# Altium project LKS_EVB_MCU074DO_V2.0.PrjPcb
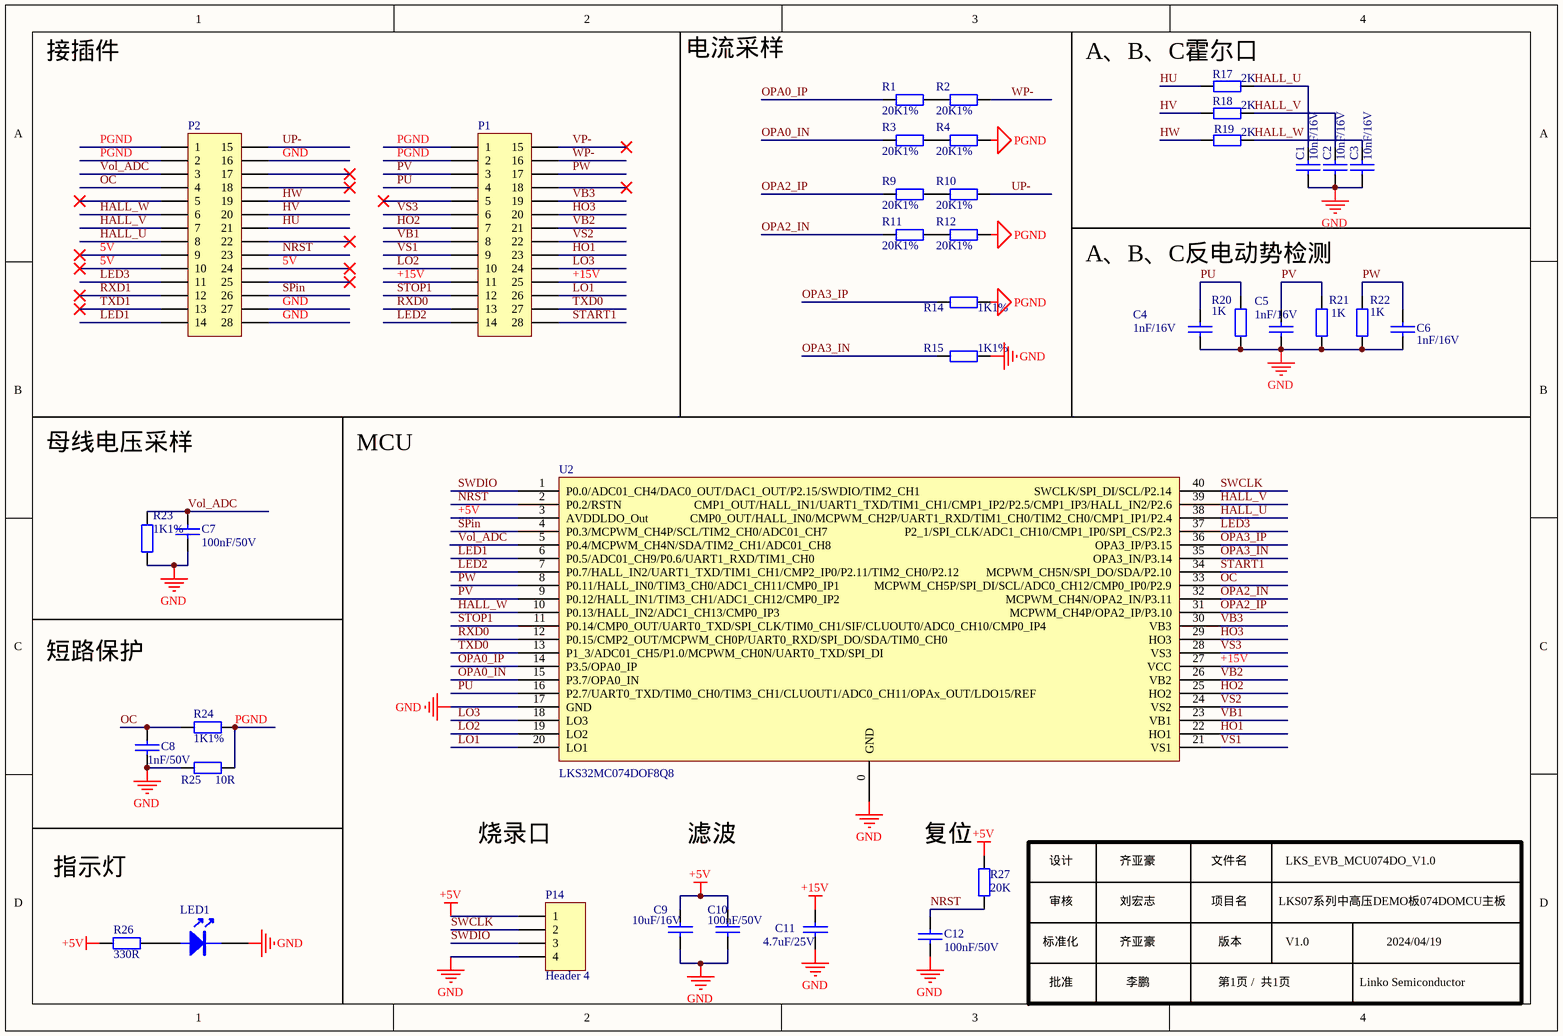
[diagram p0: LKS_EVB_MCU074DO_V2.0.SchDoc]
1 sheet, 38 parts. Net scope: global (net labels, ports and power ports of the same name join across sheets).
Board file: LKS_EVB_MCU074DO_V2.0.PcbDoc

## Sheet LKS_EVB_MCU074DO_V2.0.SchDoc
size A4; SheetNumber: 1; SheetTotal: 1

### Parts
C1  10nF/16V  [0603C]
C2  10nF/16V  [0603C]
C3  10nF/16V  [0603C]
C4  1nF/16V  [0603C]
C5  1nF/16V  [0603C]
C6  1nF/16V  [0603C]
C7  100nF/50V  [0603C]
C8  1nF/50V  [0603C]
C9  10uF/16V  [0603C]
C10  100nF/50V  [0603C]
C11  4.7uF/25V  [0603C]
C12  100nF/50V  [0603C]
LED1  LED  [LED 0603R]  (value not drawn)
P1  Header 14X2A  [HDR 2X14 底层]  (value not drawn)
P2  Header 14X2A  [HDR 2X14 底层]  (value not drawn)
P14  Header 4  [HDR1X4]
R1  20K1%  [0603R]
R2  20K1%  [0603R]
R3  20K1%  [0603R]
R4  20K1%  [0603R]
R9  20K1%  [0603R]
R10  20K1%  [0603R]
R11  20K1%  [0603R]
R12  20K1%  [0603R]
R14  1K1%  [0603R]
R15  1K1%  [0603R]
R17  2K  [0603R]
R18  2K  [0603R]
R19  2K  [0603R]
R20  1K  [0603R]
R21  1K  [0603R]
R22  1K  [0603R]
R23  1K1%  [0603R]
R24  1K1%  [0603R]
R25  10R  [0603R]
R26  330R  [0603R]
R27  20K  [0603R]
U2  LKS32MC074DOF8Q8  [QFN40]

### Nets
+5V: C9.2 C10.2 P14.1 R26.2 R27.2 U2.3(AVDDLDO_Out)
+15V: C11.2 P1.11 P1.25 U2.27(VCC)
GND: C1.2 C2.2 C3.2 C4.2 C5.2 C6.2 C7.1 C8.1 C9.1 C10.1 C11.1 C12.2 LED1.2(K) P2.16 P2.27 P2.28 P14.4 R15.1 R20.2 R21.2 R22.2 R23.1 R25.2 U2.0(GND) U2.17(GND)
PGND: P1.1 P1.2 P2.1 P2.2 R4.1 R12.1 R14.1 R24.2 R25.1
5V: P2.9 P2.10 P2.24
HALL_U: C1.1 P2.8 R17.2 U2.38(CMP0_OUT/HALL_IN0/MCPWM_CH2P/UART1_RXD/TIM1_CH0/TIM2_CH0/CMP1_IP1/P2.4)
HALL_V: C2.1 P2.7 R18.2 U2.39(CMP1_OUT/HALL_IN1/UART1_TXD/TIM1_CH1/CMP1_IP2/P2.5/CMP1_IP3/HALL_IN2/P2.6)
HALL_W: C3.1 P2.6 R19.2 U2.10(P0.13/HALL_IN2/ADC1_CH13/CMP0_IP3)
HO1: P1.23 U2.22(HO1)
HO2: P1.7 U2.25(HO2)
HO3: P1.20 U2.29(HO3)
HU: P2.21 R17.1
HV: P2.20 R18.1
HW: P2.19 R19.1
LED1: P2.14 U2.6(P0.5/ADC01_CH9/P0.6/UART1_RXD/TIM1_CH0)
LED2: P1.14 U2.7(P0.7/HALL_IN2/UART1_TXD/TIM1_CH1/CMP2_IP0/P2.11/TIM2_CH0/P2.12)
LED3: P2.11 U2.37(P2_1/SPI_CLK/ADC1_CH10/CMP1_IP0/SPI_CS/P2.3)
LO1: P1.26 U2.20(LO1)
LO2: P1.10 U2.19(LO2)
LO3: P1.24 U2.18(LO3)
NRST: C12.1 P2.23 R27.1 U2.2(P0.2/RSTN)
OC: C8.2 P2.4 R24.1 U2.33(MCPWM_CH5P/SPI_DI/SCL/ADC0_CH12/CMP0_IP0/P2.9)
OPA0_IN: R3.2 U2.15(P3.7/OPA0_IN)
OPA0_IP: R1.2 U2.14(P3.5/OPA0_IP)
OPA2_IN: R11.2 U2.32(MCPWM_CH4N/OPA2_IN/P3.11)
OPA2_IP: R9.2 U2.31(MCPWM_CH4P/OPA2_IP/P3.10)
OPA3_IN: R15.2 U2.35(OPA3_IN/P3.14)
OPA3_IP: R14.2 U2.36(OPA3_IP/P3.15)
PU: C4.1 P1.4 R20.1 U2.16(P2.7/UART0_TXD/TIM0_CH0/TIM3_CH1/CLUOUT1/ADC0_CH11/OPAx_OUT/LDO15/REF)
PV: C5.1 P1.3 R21.1 U2.9(P0.12/HALL_IN1/TIM3_CH1/ADC1_CH12/CMP0_IP2)
PW: C6.1 P1.17 R22.1 U2.8(P0.11/HALL_IN0/TIM3_CH0/ADC1_CH11/CMP0_IP1)
RXD0: P1.13 U2.12(P0.15/CMP2_OUT/MCPWM_CH0P/UART0_RXD/SPI_DO/SDA/TIM0_CH0)
RXD1: P2.12
SPin: P2.26 U2.4(P0.3/MCPWM_CH4P/SCL/TIM2_CH0/ADC01_CH7)
START1: P1.28 U2.34(MCPWM_CH5N/SPI_DO/SDA/P2.10)
STOP1: P1.12 U2.11(P0.14/CMP0_OUT/UART0_TXD/SPI_CLK/TIM0_CH1/SIF/CLUOUT0/ADC0_CH10/CMP0_IP4)
SWCLK: P14.2 U2.40(SWCLK/SPI_DI/SCL/P2.14)
SWDIO: P14.3 U2.1(P0.0/ADC01_CH4/DAC0_OUT/DAC1_OUT/P2.15/SWDIO/TIM2_CH1)
TXD0: P1.27 U2.13(P1_3/ADC01_CH5/P1.0/MCPWM_CH0N/UART0_TXD/SPI_DI)
TXD1: P2.13
UP-: P2.15 R10.1
VB1: P1.8 U2.23(VB1)
VB2: P1.21 U2.26(VB2)
VB3: P1.19 U2.30(VB3)
Vol_ADC: C7.2 P2.3 R23.2 U2.5(P0.4/MCPWM_CH4N/SDA/TIM2_CH1/ADC01_CH8)
VP-: P1.15
VS1: P1.9 U2.21(VS1)
VS2: P1.22 U2.24(VS2)
VS3: P1.6 U2.28(VS3)
WP-: P1.16 R2.1
NetLED1_1: LED1.1(A) R26.1
NetR1_1: R1.1 R2.2
NetR3_1: R3.1 R4.2
NetR9_1: R9.1 R10.2
NetR11_1: R11.1 R12.2

Not connected (* = marked no-connect by the designer): P1 5* 18*; P2 5* 17* 18* 22* 25*

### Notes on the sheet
- 接插件
- 母线电压采样
- 短路保护
- 烧录口
- 滤波
- 复位
- 指示灯
- 设计
- 审核
- 齐亚豪
- 刘宏志
- 文件名
- 项目名
- LKS07系列中高压DEMO板074DOMCU主板
- LKS_EVB_MCU074DO_V1.0
- 标准化
- 批准
- 李鹏
- 版本
- 第1页 /  共1页
- V1.0
- Linko Semiconductor
- 2024/04/19
- Labels drawn without touching a wire or pin: A、B、C反电动势检测, A、B、C霍尔口, MCU, 电流采样

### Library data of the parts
C1-C6 = CAP: Capacitor
C7-C12 = C: Capacitor
LED1 = LED: LED_Light
P1 P2 = Header 14X2A: Header, 14-Pin, Dual row
P14 = Header 4: Header, 4-Pin
R1-R4 R9-R12 R14 R15 R17-R25 R27 = Res: Resistor; Value: K
R26 = Res: Resistor; Value: 330
U2 = LKS32MC074DOF8Q8: 凌鸥创芯，芯片，96M，64kK-Flash，12K-RAM,Built-in 6N Gate Drive+ldo5v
